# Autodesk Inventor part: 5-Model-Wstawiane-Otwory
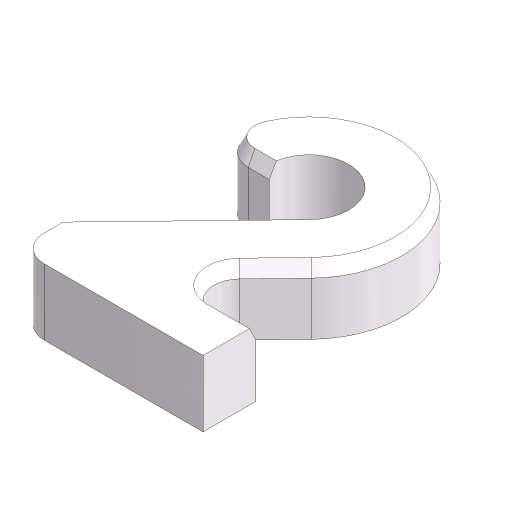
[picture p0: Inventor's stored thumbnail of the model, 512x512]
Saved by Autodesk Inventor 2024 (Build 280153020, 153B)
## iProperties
Company: ATC
Shininess: 21.0
Length Units: 11269
Angle Units: 11279
Time Units: 11290
Mass Units: 11283
Compacted: True
Created: 2023-03
Part Number: 5-Model-Wstawiane-Otwory
Document SubType Name: Modeling
Designer: Andrzej Jaskulski
Material: Kurs-AJ
Density: 1 g/cm^3
Appearance: Kurs-AJ
Checked By: A.J.
Engr Approved By: Andrzej Jaskulski
Mfg Approved By: Andrzej Jaskulski
Authority: A.J.
Density: 0.0
Volumn: 0.0
Area: 0.0
PropertySet Name: Model Information
Control State: 0
Master: False
Checked Out: False
Title: A.J.: Kurs R2024-MEP
Author: Andrzej Jaskulski
Revision Number: 1/24
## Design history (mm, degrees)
sketch "Zarys dwójki"
  geometry: L1 (0, 150)-(40, 150); L2 (140, 0)-(140, 40); L3 (140, 40)-(61.086, 40); L4 (61.086, 40)-(120.354, 101.374); L5 (91.58, 129.16)-(0, 34.326); L6 (140, 0)-(0, 0); L7 (0, 0)-(0, 34.326); A1 r 30 centre (70, 150) between (91.58, 129.16) and (40, 150); A2 r 70 centre (70, 150) between (120.354, 101.374) and (0, 150)
  constraints: 14 end point, 4 point on circle, 3 perpendicular, 2 centre point, 2 parallel, 2 tangent, 1 coincident, 1 horizontal, 1 point on line, 1 other
  dimensions: "d21" = 70 radius of A2; "d22" = 40 distance of L2.start L2.end (= Y); "d23" = 140 distance of L2.start L6.end (= X); "d24" = 150 distance from line of A1.centre L6; "d25" = 70 horizontal distance of A1.centre L6.end; "d26" = 34.32618 distance of L6.end L5.end; "d27" = 40 radial gap between concentric circles of A2 A1 (= d22)
extrude "Dwójka" new body sketch "Zarys dwójki" distance "d7" = 50 (= Z); taper "d8" = 0 deg
node "Oś walca"
node "Bryła1"
node "Korpusy bryłowe"
node "Korpusy powierzchniowe"
fillet "Zaokrąglenie1" dims "d12" = 20
chamfer "Faza1" distance "d13" = 5; stored, may be unused: second distance "d14" = 10, angle "d15" = 45 deg
other parameters: "d9" = 90 deg, "X" = 140 [user parameter; used in 1 equation term], "Y" = 40 [user parameter; used in 1 equation term], "Z" = 50 [user parameter; used in 1 equation term]
